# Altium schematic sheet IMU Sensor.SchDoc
size A4
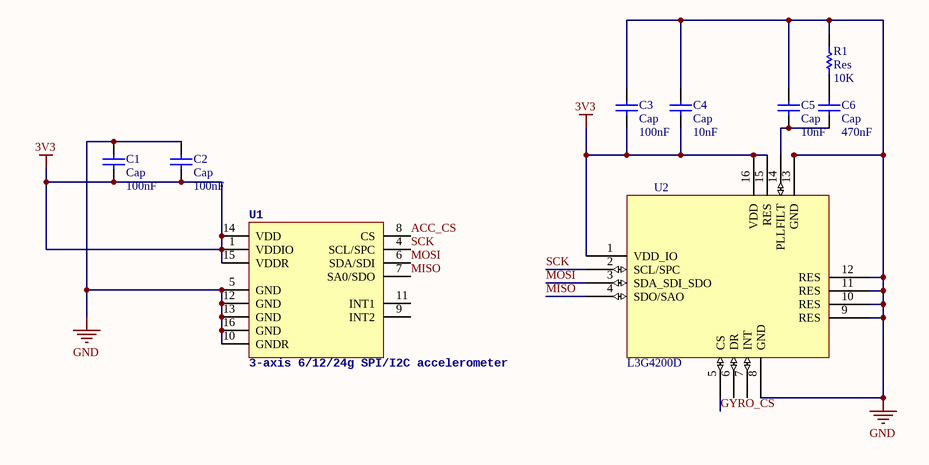
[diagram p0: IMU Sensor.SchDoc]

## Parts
C1  Cap  value 100nF  [0603-CAP]
C2  Cap  value 100nF  [0603-CAP]
C3  Cap  value 100nF  [0603-CAP]
C4  Cap  value 10nF  [0603-CAP]
C5  Cap  value 10nF  [0603-CAP]
C6  Cap  value 470nF  [0603-CAP]
R1  Res  value 10K  [0603-RES]
U1  3-axis 6/12/24g SPI/I2C accelerometer  [LGA16-3MM]
U2  L3G4200D  [L3G4200D]

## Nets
3V3: C1.1 C2.1 C3.1 C4.1 U1.1(VDDIO) U1.14(VDD) U1.15(VDDR) U2.1(VDD_IO) U2.15(RES) U2.16(VDD)
GND: C1.2 C2.2 C3.2 C4.2 C5.1 R1.2 U1.5(GND) U1.10(GNDR) U1.12(GND) U1.13(GND) U1.16(GND) U2.8(GND) U2.9(RES) U2.10(RES) U2.11(RES) U2.12(RES) U2.13(GND)
ACC_CS: U1.8(CS)
GYRO_CS: U2.5(CS)
MISO: U1.7(SA0/SDO) U2.4(SDO/SAO)
MOSI: U1.6(SDA/SDI) U2.3(SDA_SDI_SDO)
SCK: U1.4(SCL/SPC) U2.2(SCL/SPC)
NetC5_2: C5.2 C6.1 U2.14(PLLFILT)
NetC6_2: C6.2 R1.1

Not connected (* = marked no-connect by the designer): U1 9(INT2) 11(INT1); U2 6(DR) 7(INT)

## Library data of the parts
C1-C6 = Cap: Capacitor
R1 = Res: Resistor
U1 = LIS331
